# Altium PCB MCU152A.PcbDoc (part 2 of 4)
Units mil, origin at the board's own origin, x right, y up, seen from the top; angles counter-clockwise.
Board outline 2307.9 x 3007.9 mil, 4 copper layers (Top Signal, GND, PWR, Bottom Signal), stack 61.6 mil thick; 198 components, 136 nets, 740 pads, 401 vias.
Unrouted connection lines stored in the file: 147.
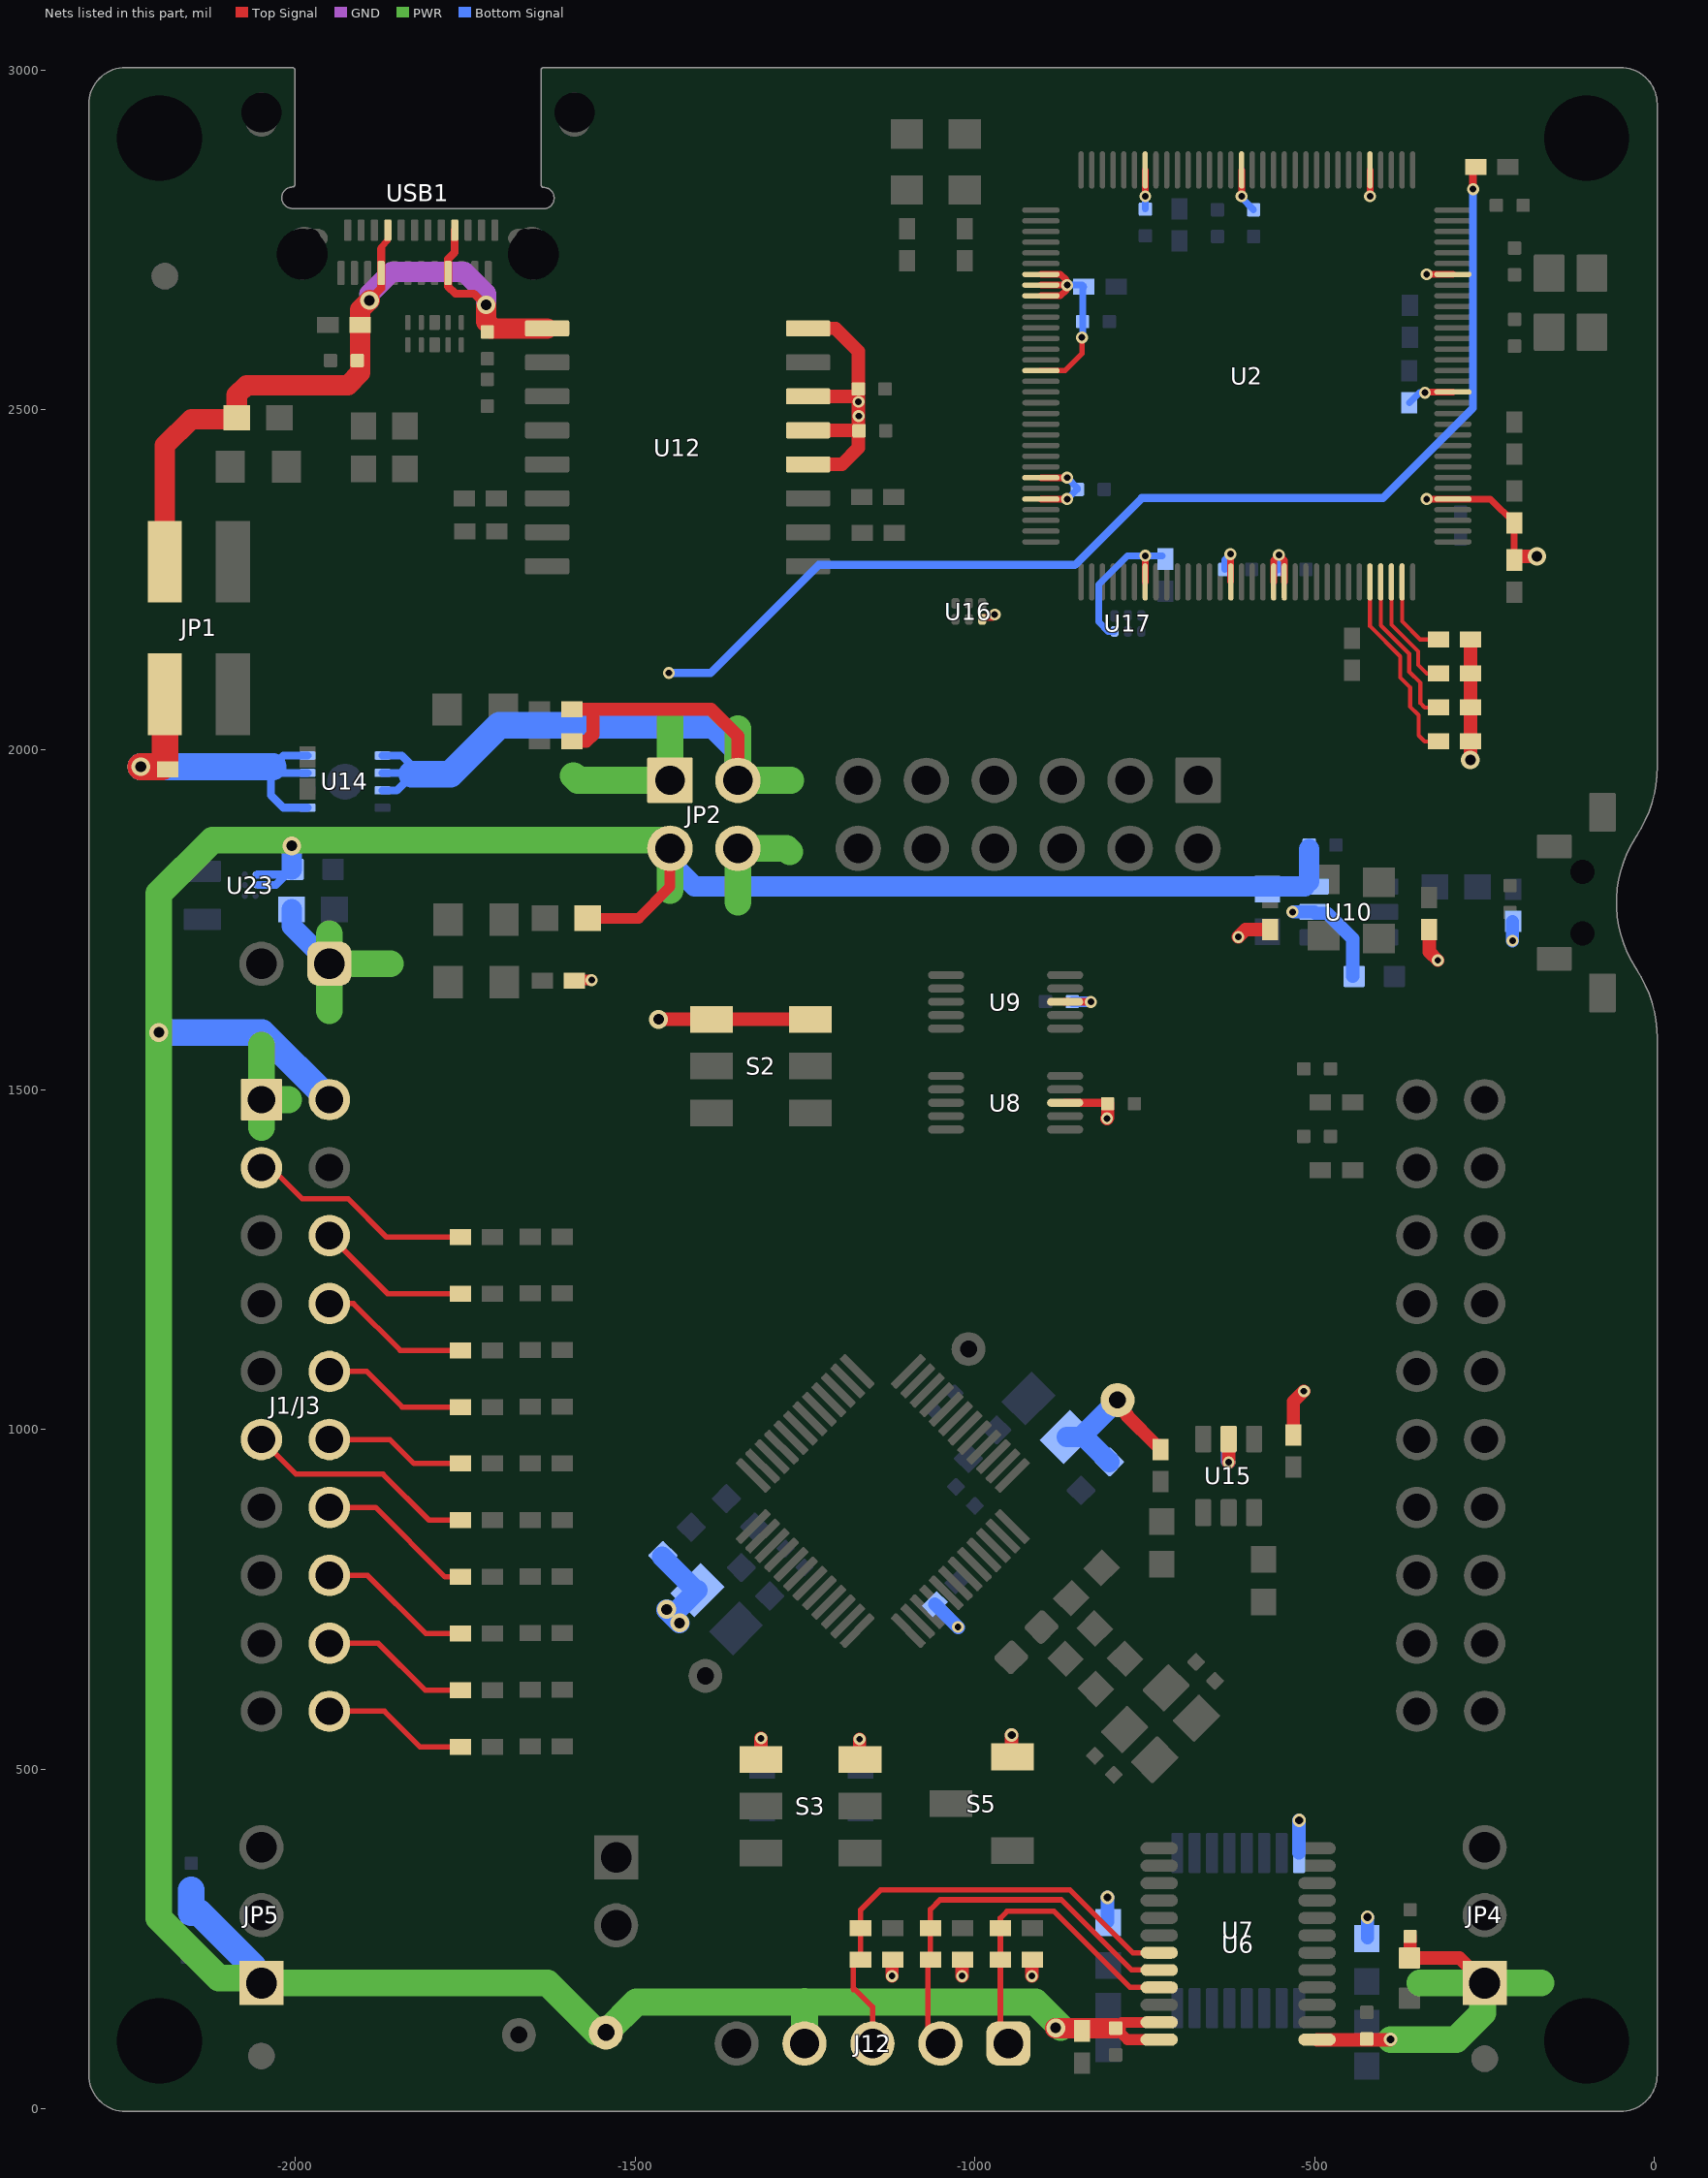
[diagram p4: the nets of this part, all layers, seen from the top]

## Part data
C1 C2 C5 C10 C11 C43 C45 C56 C57 C58 C59 C69 C70 C75 C77: library part CMP-0090362-1, "0.1µF ±10% 10V Ceramic Capacitor X7R 0402 (1005 Metric)", Digikey Part Number=732-7513-1-ND, Manufacturer="Wurth Electronics", Mouser Part Number=710-885012205018, Operating Temperature Range="-55°C to +125°C", TempCo=15%, Temperature Characteristic=X7R, Tolerance_%=10%, ValueDisplayed=100000pF
C3 C4 C78 C79: library part CMP-0124909-1, "12 pF ±2% 50V Ceramic Capacitor C0G, NP0 0402 (1005 Metric)", Digikey Part Number=732-885392005127CT-ND, Manufacturer=Wurth, Mouser Part Number=710-885392005127, Operating Temperature Range="-55°C to +125°C", TempCo=30ppm/°C, Temperature Characteristic=NP0, Tolerance_%=2%, ValueDisplayed=12pF
C6 C35 C36: library part CMP-0124925-1, "2.2 µF ±20% 10V Ceramic Capacitor X5R 0603 (1608 Metric)", Digikey Part Number=732-7908-1-ND, Manufacturer="Wurth Electronics", Mouser Part Number=710-885012106011, Operating Temperature Range="-55°C to +85°C", TempCo=15%, Temperature Characteristic=X5R, Tolerance_%=20%, ValueDisplayed=2.2uF
C7 C8 C9 C13 C14 C15 C17 C21 C22 C23: library part CMP-0006456-2, "CAP, CERM, 330 pF, 50 V, +/- 5%, C0G/NP0, 0402", Cap_Case=0402, Manufacturer=MuRata, Supplier Part Number 1=490-1295-1-ND, TempCo=C0G/NP0, Tolerance_%=5%, Value1=Unknown, Value2=50V, ValueDisplayed=330pF
C12 C18 C19 C20 C63: library part CMP-0006231-2, "CAP, CERM, 1000 pF, 50 V, +/- 10%, X7R, 0402", Cap_Case=0402, Manufacturer="Wurth Elektronik", Supplier Part Number 1=732-7556-1-ND, TempCo=X7R, Tolerance_%=10%, Value1=Unknown, Value2=50V, ValueDisplayed=1000pF
C28 C29 C30 C80 C120: library part CMP-0124926-1, "10 µF ±20% 25V Ceramic Capacitor X5R 0603 (1608 Metric)", Manufacturer=Wurth, Operating Temperature Range="-55°C to +85°C", TempCo=15%, Temperature Characteristic=X5R, Tolerance_%=20%, ValueDisplayed=10uF
C31 C32 C34 C37 C38 C81 C124: library part CMP-0090362-1, "0.1µF ±10% 10V Ceramic Capacitor X7R 0402 (1005 Metric)", Digikey Part Number=732-7513-1-ND, Manufacturer="Wurth Electronics", Mouser Part Number=710-885012205018, Operating Temperature Range="-55°C to +125°C", TempCo=15%, Temperature Characteristic=X7R, Tolerance_%=10%, ValueDisplayed=0.1uF
C60: library part CMP-0092424-1, "Cap Cer 3300pF 50V X7R 0402", Digikey Part Number=732-7559-1-ND, Manufacturer="Wurth Electronics", Mouser Part Number=710-885012205064, Operating Temperature Range="-55°C to +125°C", TempCo=15%, Temperature Characteristic=X7R, Tolerance_%=10%, ValueDisplayed=3.3nF
C62 C71 C72 C74 C76: library part CMP-0064924-2, "CAP, CERM, 1 uF, 10 V,+/- 20%, X5R, 0402", Cap_Case=0402, Manufacturer="Wurth Elektronik", Supplier Part Number 1=732-7489-1-ND, TempCo=X5R, Tolerance_%=20%, Value1=Unknown, Value2=10V, ValueDisplayed=1uF
C64: library part CMP-0006268-2, "CAP, CERM, 4.7 uF, 10 V, +/- 10%, X5R, 0402", Cap_Case=0402_065, Manufacturer=TDK, Supplier Part Number 1=445-13820-1-ND, TempCo=X5R, Tolerance_%=10%, Value1="0.003417 ohm", Value2=10V, ValueDisplayed=4.7uF
C65 C66 C67 C68 C73: library part CMP-0090363-1, "10000pF ±10% 25V Ceramic Capacitor X7R 0402 (1005 Metric)", Digikey Part Number=732-7545-1-ND, Manufacturer="Wurth Electronics", Mouser Part Number=710-885012205050, Operating Temperature Range="-55°C to +125°C", TempCo=15%, Temperature Characteristic=X7R, Tolerance_%=10%, ValueDisplayed=10000pF
C119: library part CMP-0006825-5, "CAP, CERM, 2.2 uF, 16 V, +/- 20%, X5R, 0603", Cap_Case=0603, Manufacturer="Wurth Elektronik", Supplier Part Number 1=732-7915-1-ND, TempCo=X5R, Tolerance_%=20%, Value1=Unknown, Value2=16V, ValueDisplayed=2.2uF
C125: library part CMP-0124908-1, "10000 pF ±10% 16V Ceramic Capacitor X7R 0603 (1608 Metric)", Digikey Part Number=732-7959-1-ND, Manufacturer=Wurth, Mouser Part Number=710-885012206040, Operating Temperature Range="-55°C to +125°C", TempCo=15%, Temperature Characteristic=X7R, Tolerance_%=10%, ValueDisplayed=10nF
"CE Logo1": library part CMP-0074844-1
FID1 FID2 FID3 FID4 FID5 FID6: library part CMP-0077181-1, "Fiducial mark.  There is nothing to buy or mount.", Manufacturer=N/A
H1 H2: library part CMP-0077978-1, "Spacer Support, Nylon 66", Manufacturer="Kang Yang"
J1/J3: library part CMP-0003837-4, "Receptacle, 2.54mm, 10x2, Tin, TH", Alternate Manufacturer="Major League Electronics", Alternate PartNumber=CRD-081413-A-G, Manufacturer=Samtec, Supplier Part Number 1=SAM1204-10-ND
J4/J2: library part CMP-0078266-4, "Receptacle, 2.54mm, 10x2, Tin, TH", Alternate Manufacturer="Major League Electronics", Alternate PartNumber=CRD-081413-A-G, Manufacturer=Samtec, Supplier Part Number 1=SAM1204-10-ND
J12: library part CMP-0084909-1, "Header, 2.54mm, 5x1, Gold, TH", Color=Black, Current_A=3A, Manufacturer="Wurth Elektronik", Voltage_V=250V
J15: library part CMP-0054794-1, "Header, 2.54 mm, 2x1, Gold, TH", Manufacturer="Wurth Elektronik", Supplier Part Number 1=732-5315-ND
J17: library part CMP-0054794-2, "Header, 2.54 mm, 2x1, Gold, TH", Color=Black, Manufacturer="Wurth Elektronik", Supplier Part Number 1=732-5315-ND
J101: library part CMP-0092423-1, "THT Vertical Pin Header WR-PHD, Pitch 2.54 mm, Dual Row, 12 pins", Current_A=3A, Digikey Part Number=732-5297-ND, Manufacturer="Wurth Electronics", Mouser Part Number=710-61301221121, Operating Temperature Range="-40°C to +105°C", Voltage_V=250V
JP1: library part CMP-0055559-1, "Header, 2.54mm, 2x2, Gold, SMT", Color=Black, Manufacturer=Samtec, Supplier Part Number 1=TSM-102-01-L-DV-ND, Voltage_V=475V
JP2: library part CMP-0092422-1, "THT Vertical Pin Header WR-PHD, Pitch 2.54 mm, Dual Row, 4 pins", Current_A=3A, Digikey Part Number=732-5294-ND, Manufacturer="Wurth Electronics", Mouser Part Number=710-61300421121, Operating Temperature Range="-40°C to +105°C", Voltage_V=250V
JP4 JP5: library part CMP-0054796-1, "Header, 2.54 mm, 3x1, Gold, TH", Manufacturer="Wurth Elektronik", Supplier Part Number 1=732-5316-ND
L1: library part CMP-0003073-1, "Ferrite Bead, 220 ohm @ 100 MHz, 2 A, 0805", Manufacturer="Wurth Elektronik", Supplier Part Number 1=732-1614-1-ND, Value1="0.05 ohm", Value2=2A, ValueDisplayed="220 ohm"
L2: library part CMP-0003093-1, "Ferrite Bead, 60 ohm @ 100 MHz, 3 A, 0805", Manufacturer="Wurth Elektronik", Supplier Part Number 1=732-1612-1-ND, Value1="0.025 ohm", Value2=3A, ValueDisplayed="60 ohm"
L4: library part CMP-0124907-1, "Inductor Power Shielded Multi-Layer 1uH 20% 1MHz 14Q-Factor Powdered Iron 1.2A 180mOhm DCR 0805 T/R", Digikey Part Number=732-5056-1-ND, Manufacturer=Wurth, Mouser Part Number=710-74479773210, Operating Temperature Range="-40°C to +125°C", Self Resonant Frequency=90MHz, Test Frequency=1MHz, Tolerance_%=20%
LED0 LED1 LED4 LED6 LED7: library part CMP-0002951-3, "LED, Red, SMD", Color=Red, Manufacturer="Wurth Elektronik", Power_TotalModule=72mW, Value1=0.072W, Value2=1.9V
LED2 LED3: library part CMP-0002959-3, "LED, Blue, SMD", Color=Blue, Manufacturer="Wurth Elektronik", Power_TotalModule=105mW, Value1=0.105W, Value2=3.2V
LED5: library part CMP-0003014-3, "LED, Green, SMD", Color=Green, Manufacturer="Wurth Elektronik", Power_TotalModule=105mW, Value1=0.105W, Value2=3.2V
Logo1 Logo4: library part CMP-0074838-1, "Texas Instrument Corporate Signature"
Logo2: library part CMP-0074847-1, "FCC_disclaimer"
Logo3: library part CMP-0074769-1
M4 M5 M6 M7 M8 M9 M10 M11 M12 M13: library part CMP-0003761-2, "Shunt, 2.54mm, Gold, Black", Manufacturer="Wurth Elektronik", Supplier Part Number 1=732-2678-ND
MH1 MH2 MH3 MH4: library part CMP-0078424-2, "PCB Mounting Hole, No Pad", Manufacturer=Any, PartNumber=N/A
R1 R2 R6 R21 R22 R23 R27 R28 R29 R30 R32 R33 R55 R56 R57 R58: library part CMP-0027004-2, "RES, 0, 5%, 0.063 W, 0402", Manufacturer="Yageo America", Power_W=63mW, Supplier Part Number 1=311-0.0JRCT-ND, TempCo="200 ppm/C", Tolerance_%=5%, Value2=0.063W, Value_Code=0000, ValueDisplayed=0
R3 R7: library part CMP-0026826-2, "RES, 10 M, 5%, 0.063 W, AEC-Q200 Grade 0, 0402", Manufacturer=Vishay-Dale, Power_W=63mW, Supplier Part Number 1=541-10MJCT-ND, TempCo="200 ppm/C", Tolerance_%=5%, Value2=0.063W, Value_Code=10M0, ValueDisplayed=10M
R4 R5 R62 R64: library part CMP-0026962-3, "RES, 680, 5%, 0.063 W, AEC-Q200 Grade 0, 0402", Manufacturer=Vishay-Dale, Power_W=63mW, Supplier Part Number 1=541-680JCT-ND, TempCo="200 ppm/C", Tolerance_%=5%, Value2=0.063W, Value_Code=680R, ValueDisplayed=680
R8 R9 R11 R12 R13 R14 R18 R19: library part CMP-0025697-4, "RES, 0, 5%, 0.1 W, AEC-Q200 Grade 0, 0603", Manufacturer=Vishay-Dale, Power_W=100mW, Supplier Part Number 1=541-0.0GCT-ND, TempCo="200 ppm/C", Tolerance_%=5%, Value2=0.1W, Value_Code=0000, ValueDisplayed=0
R10: library part CMP-0023387-3, "RES, 50, 0.1%, 0.125 W, 0603", Manufacturer="Vishay Thin Film", Power_W=125mW, Supplier Part Number 1=FC0603-50BFCT-ND, TempCo="25 ppm/C", Tolerance_%=0.1%, Value2=0.125W, Value_Code=50R0, ValueDisplayed=50
R15 R16: library part CMP-0022746-5, "RES, 10.0 k, 1%, 0.1 W, 0603", Manufacturer=Yageo, Power_W=100mW, Supplier Part Number 1=311-10.0KHRCT-ND, TempCo="100 ppm/C", Tolerance_%=1%, Value2=0.1W, Value_Code=10k0, ValueDisplayed=10.0k
R17: library part CMP-0025769-4, "RES, 2.2 k, 5%, 0.1 W, AEC-Q200 Grade 0, 0603", Manufacturer=Vishay-Dale, Power_W=100mW, Supplier Part Number 1=541-2.2KGCT-ND, TempCo="200 ppm/C", Tolerance_%=5%, Value2=0.1W, Value_Code=2k20, ValueDisplayed=2.2k
R24 R25 R26 R66 R67 R68 R69: library part CMP-0026071-3, "RES, 1.00 k, 1%, 0.063 W, AEC-Q200 Grade 0, 0402", Manufacturer=Vishay-Dale, Power_W=63mW, Supplier Part Number 1=541-1.00KLCT-ND, TempCo="100 ppm/C", Tolerance_%=1%, Value2=0.063W, Value_Code=1k00, ValueDisplayed=1.00k
R31 R35: library part CMP-0026890-5, "RES, 2.2 k, 5%, 0.063 W, AEC-Q200 Grade 0, 0402", Manufacturer=Vishay-Dale, Power_W=63mW, Supplier Part Number 1=541-2.2KJCT-ND, TempCo="200 ppm/C", Tolerance_%=5%, Value2=0.063W, Value_Code=2k20, ValueDisplayed=2.2k
R53: library part CMP-0026100-2, "RES, 1.00 M, 1%, 0.063 W, AEC-Q200 Grade 0, 0402", Manufacturer=Vishay-Dale, Power_W=63mW, Supplier Part Number 1=541-1.00MLCT-ND, TempCo="100 ppm/C", Tolerance_%=1%, Value2=0.063W, Value_Code=1M00, ValueDisplayed=1.00M
R54 R61: library part CMP-0025921-5, "RES, 3.0 k, 5%, 0.1 W, 0603", Manufacturer=Yageo, Power_W=100mW, Supplier Part Number 1=311-3.0KGRCT-ND, TempCo="100 ppm/C", Tolerance_%=5%, Value2=0.1W, Value_Code=3k00, ValueDisplayed=3.0k
R59 R60: library part CMP-0025932-5, "RES, 5.1 k, 5%, 0.1 W, 0603", Manufacturer=Yageo, Power_W=100mW, Supplier Part Number 1=311-5.1KGRCT-ND, TempCo="100 ppm/C", Tolerance_%=5%, Value2=0.1W, Value_Code=5k10, ValueDisplayed=5.1k
R70: library part CMP-0026824-3, "RES, 100, 5%, 0.063 W, AEC-Q200 Grade 0, 0402", Manufacturer=Vishay-Dale, Power_W=63mW, Supplier Part Number 1=541-100JCT-ND, TempCo="200 ppm/C", Tolerance_%=5%, Value2=0.063W, Value_Code=100R, ValueDisplayed=100
R71: library part CMP-0026918-5, "RES, 3.3 k, 5%, 0.063 W, AEC-Q200 Grade 0, 0402", Manufacturer=Vishay-Dale, Power_W=63mW, Supplier Part Number 1=541-3.3KJCT-ND, TempCo="200 ppm/C", Tolerance_%=5%, Value2=0.063W, Value_Code=3k30, ValueDisplayed=3.3k
R72 R73: library part CMP-0026736-1, "RES, 470, 1%, 0.063 W, 0402", Manufacturer="Yageo America", Power_W=63mW, Supplier Part Number 1=311-470LRCT-ND, TempCo="100 ppm/C", Tolerance_%=1%, Value2=0.063W, Value_Code=470R, ValueDisplayed=470
R74 R75: library part CMP-0026825-5, "RES, 10 k, 5%, 0.063 W, AEC-Q200 Grade 0, 0402", Manufacturer=Vishay-Dale, Power_W=63mW, Supplier Part Number 1=541-10KJCT-ND, TempCo="200 ppm/C", Tolerance_%=5%, Value2=0.063W, Value_Code=10k0, ValueDisplayed=10k
R76: library part CMP-0026413-2, "RES, 4.87 k, 1%, 0.063 W, AEC-Q200 Grade 0, 0402", Manufacturer=Vishay-Dale, Power_W=63mW, Supplier Part Number 1=541-4.87KLCT-ND, TempCo="100 ppm/C", Tolerance_%=1%, Value2=0.063W, Value_Code=4k87, ValueDisplayed=4.87k
R77: library part CMP-0026946-3, "RES, 51, 5%, 0.063 W, AEC-Q200 Grade 0, 0402", Manufacturer=Vishay-Dale, Power_W=63mW, Supplier Part Number 1=541-51JCT-ND, TempCo="200 ppm/C", Tolerance_%=5%, Value2=0.063W, Value_Code=51R0, ValueDisplayed=51
R94: library part CMP-0023133-5, "RES, 47.0 k, 1%, 0.1 W, 0603", Manufacturer=Yageo, Power_W=100mW, Supplier Part Number 1=311-47.0KHRCT-ND, TempCo="100 ppm/C", Tolerance_%=1%, Value2=0.1W, Value_Code=47k0, ValueDisplayed=47.0k
R95: library part CMP-0025874-4, "RES, 0, 5%, 0.1 W, AEC-Q200 Grade 0, 0603", Manufacturer=Panasonic, Power_W=100mW, Supplier Part Number 1=P0.0GCT-ND, TempCo="600 ppm/C", Tolerance_%=5%, Value2=0.1W, Value_Code=0000, ValueDisplayed=0
S1: library part CMP-0002328-1, "Switch, SPST, 0.05 A, 12 VDC, SMD", CurrentRating_mA=50A, Manufacturer=Diptronics
S2 S3: library part CMP-0002233-1, "Switch, Dual SPDT,  2 Pos, 0.1A, 6VDC, SMD", CurrentRating_mA=100A, Manufacturer="Copal Electronics", Supplier Part Number 1=CASD20JCT-ND
S5: library part CMP-0002139-2, "Switch, Slide, SPDT  100mA, SMT", CurrentRating_mA=100A, Manufacturer="Copal Electronics", Supplier Part Number 1=CAS120JCT-ND
TP2 TP3 TP4 TP5 TP6: library part CMP-0078143-3, "TEST POINT.  No entry in BOM.", Manufacturer=N/A
U1: library part CMP-0125361-1, "F28E12x Real-Time Microcontrollers", Frequency_Fixed=160MHz, Manufacturer="Texas Instruments", Max Supply Voltage=3.63V, Min Supply Voltage=2.8V, Operating Temperature Range="-40°C to +125°C"
U2: library part CMP-0077953-1, "MSP432E401YTPDT, PDT0128A (TQFP-128)", Alternate Manufacturer="Texas Instruments", Alternate PartNumber=MSP432E401YTPDTR
U6: library part CMP-0066458-2, "8-Bit Dual-Supply Bus Transceiver with Configurable Voltage-Level Shifting and Three-State Outputs, PW0024A (TSSOP-24)", Alternate Manufacturer="Texas Instruments", Operating Temperature Range="-40 to 85 C", Rating=Catalog
U7: library part CMP-0089841-1, "3 Circuit IC Switch 2:1 75Ohm 16-TSSOP", Digikey Part Number=296-3833-1-ND, Manufacturer="Texas Instruments", Max Supply Voltage=5.5V, Min Supply Voltage=2V, Mouser Part Number=595-SN74LV4053APWR, Nominal Supply Current=20uA, On State Resistance=100-225Ω, Operating Temperature Range="-40°C to +85°C"
U8 U9: library part CMP-0067418-1, "DUAL 10-Ohm SPDT ANALOG SWITCH, DGS0010A (VSSOP-10)", Alternate Manufacturer="Texas Instruments", Alternate PartNumber=TS5A23157DGST
U10: library part CMP-0120241-1, "Low-quiescent current supervisor with programmable delay and manual reset 6-SOT-23 -40 to 85", Manufacturer="Texas Instruments", Max Supply Voltage=6V, Min Supply Voltage=1.7V, Nominal Supply Current=0.6uA, Operating Temperature Range="-40°C to +125°C", Threshold Voltage=3.07V
U12: library part CMP-0091303-1, "Full/Low Speed Isolated USB Repeater, SOIC16-Wide", Manufacturer="Texas Instruments", Max Supply Voltage=5.5V, Min Supply Voltage=3V, Nominal Supply Current=9-9.5mA, Operating Temperature Range="-55°C to +150°C"
U13: library part CMP-0073613-3, "4-Channel Ultra-Low-Capacitance IEC ESD Protection Diode, DQA0010A (USON-10)", Alternate Manufacturer="Texas Instruments"
U14: library part CMP-0124913-1, "Low-Noise, Wide-Bandwidth, High PSRR, Low-Dropout 1-A Linear Regulator", Digikey Part Number=296-52139-1-ND, Dropout Voltage=500mV, Manufacturer="Texas Instruments", Max Supply Voltage=6.5V, Min Supply Voltage=3.8V, Mouser Part Number=595-TPS7A8033DRBR, Nominal Supply Current=120uA, Operating Temperature Range="-40°C to +125°C", Output Voltage=3.3V
U15: library part CMP-0051789-2, "Dual Buffer/Driver with Open-Drain Output, DBV0006A, LARGE T&R", F @ Nom Voltage(Max)(Mhz)=150, Generic Part Number=SN74LVC2G07, ICC @ Nom Voltage(Max)(mA)=0.01, Manufacturer="Texas Instruments", Operating Temperature Range(C)="-40 to 125", Rating=Catalog, tpd @ Nom Voltage(Max)(ns)=8.6,4.4,3.7,2.9, Voltage(Nom)(V)=1.8,2.5,3.3,5
U16 U17: library part CMP-0043115-3, "4-Channel ESD Protection Array for High-Speed Data Interfaces, DRY0006A (USON-6)", Breakdown Voltage(Min)(V)=6, IO Capacitance(Typ)(pF)=1.6, IO Leakage Current(nA)=1, Manufacturer="Texas Instruments", Operating Temperature Range="-40 to 85 C", Rating=Catalog
U23: library part CMP-0067212-2, "5V, 500mA, 4MHz Step-Up DC/DC Converter, YFF0006AEAE (DSBGA-6)", Alternate Manufacturer="Texas Instruments", Alternate PartNumber=TPS61241YFFT, Operating Temperature Range="-40 to 85 C", Rating=Catalog
USB1: library part CMP-0092137-1, "Connector, USB Type-C 24 pin Mid Mount dual row Receptacle Surface Mount", Manufacturer=MUP, Operating Temperature Range="-25°C to +85°C"
Y1: library part CMP-0093781-1, "20 MHz ±10ppm Crystal 8pF 50 Ohms 4-SMD, No Lead", Digikey Part Number=1923-830108207209CT-ND, Frequency Stability=20ppm, Frequency Tolerance=10ppm, Frequency_Fixed=20MHz, Load Capacitance=8pF, Manufacturer="Wurth Electronics", Mouser Part Number=710-830108207209, Operating Temperature Range="-40°C to +85°C"
Y2: library part CMP-0094478-1, "Crystal 16 MHz ±20ppm Crystal 8pF 70 Ohms 4-SMD, No Lead", Digikey Part Number=732-830064296CT-ND, Frequency Stability=20ppm, Frequency_Fixed=16MHz, Load Capacitance=8pF, Manufacturer=Wurth, Mouser Part Number=710-830064296, Operating Temperature Range="-10°C to +70°C"
ZZ1: library part CMP-0077236-1
ZZ2: library part CMP-0077237-1
ZZ3: library part CMP-0077238-1

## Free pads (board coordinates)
  round 60 on Mech5: 4(-2200,100) 4(-2050,77.66) 4(-250,73.69) 4(-100,100)

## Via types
v1: diameter 17.72, hole 9.84, Top Signal to Bottom Signal, tented both sides, 368 vias
v2: diameter 27.56, hole 15.75, Top Signal to Bottom Signal, tented both sides, 21 vias
v3: diameter 19.68, hole 11.81, Top Signal to Bottom Signal, tented both sides, 6 vias
v4: diameter 19.68, hole 7.87, Top Signal to Bottom Signal, tented both sides, 4 vias
v5: diameter 15.75, hole 7.87, Top Signal to Bottom Signal, tented both sides, 2 vias

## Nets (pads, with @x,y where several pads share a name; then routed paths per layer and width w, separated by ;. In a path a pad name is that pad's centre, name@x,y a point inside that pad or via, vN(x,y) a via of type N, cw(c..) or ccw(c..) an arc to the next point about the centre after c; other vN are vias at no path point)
+3V3_MCU: C5.2 C10.1 C28.1 C29.1 C34.1 C35.1 C43.1 C45.1 C119.1 C125.2 J1/J3.1 J17.1 JP2.4 JP4.1 L1.1 L2.1 R3.2 R4.2 R5.2 R7.2 R14.2 R17.2 R31.2 R35.2 R62.2 S2.1 S2.4 S3.3 S3.6 S5.3 TP4.1 U6.1 U7.16 U8.8 U9.8 U10.5 U15.5 | length 2754.5
  Top Signal w11.81: U8.8@-867.32,1480.5 C45.1@-806.18,1480.5 ; U9.8@-867.32,1629 v1(-829.51,1629)
  Top Signal w15.75: R62.2@-1588.62,1661 v1(-1564.04,1661)
  Top Signal w19.68: v2(-1465.7,1603.21) S2.1@-1387.69,1603.21 S2.4@-1242.02,1603.21 ; S3.6@-1314.85,514.17 v1(-1314.85,545.11) ; S3.3@-1169.85,514.81 v1(-1169.85,543.9) ; v3(-946,550) -946,512.95 S5.3@-943.5,510.45 ; v1(-805.72,1457.39) -804.68,1458.43 C45.1@-804.68,1479 ; TP4.1@-790.17,1043 -790.17,1034.8 -775.92,1020.55 -775.92,1019.51 -732.61,976.19 -728.67,976.19 -726.7,974.22 R3.2@-726.7,970.28 ; v1(-626.7,951.46) U15.5@-626.7,985.59 ; v1(-612.4,1724.53) -601.76,1735.17 R4.2@-565.85,1735.17 ; R7.2@-531.44,991.53 -531.44,1040.56 v1(-516,1056) ; U6.1@-496.25,101.39 v3@-389,101.39 ; C28.1@-360.65,221.81 -286.81,221.81 JP4.1@-250,185 ; C28.1@-359.68,224.55 C34.1@-359.68,253.55 ; R5.2@-331.49,1735.17 -331.49,1702.51 v1(-319,1690.02)
  PWR w39.37: -2050,1444 J1/J3.1@-2050,1485 ; -2050,1565 J1/J3.1@-2050,1485 ; J1/J3.1@-2048,1483 J1/J3.1@-2050,1485 ; -2010,1485 J1/J3.1@-2050,1485 ; -1950,1616 J17.1@-1950,1685 ; -1950,1729 J17.1@-1950,1685 ; -1860,1685 J17.1@-1950,1685 ; -1348.85,1775.95 JP2.4@-1348.85,1855 -1277.69,1855 -1272.69,1850 ; v3(-388.39,102) -292,102 -253,141 JP4.1@-253,185 ; -345.46,185 JP4.1@-253,185 ; -166.75,185 JP4.1@-250,185 JP4.1@-253,185
  Bottom Signal w15.75: C43.1@-856.44,1629 v1(-829.51,1629)
  Bottom Signal w19.68: R31.2@-1059.11,742.7 v1@-1024.87,708.46 ; R17.2@-805,275 v3(-805,311) ; C5.2@-627.95,981.45 -627.95,952.71 v1(-626.7,951.46) ; v1@-531,1761.32 U10.5@-500.81,1761.32 -498.85,1759.35 -481.69,1759.35 -444.05,1721.71 C125.2@-444.05,1666.45 ; U7.16@-523.18,376.36 v3@-523.18,424.5 ; R14.2@-422.47,251.52 v3(-422.47,282) ; v1(-209,1719) R35.2@-209,1746.57
  Bottom Signal w30: C119.1@-2005.5,1765 -2005.5,1740.5 J17.1@-1950,1685 ; C35.1@-1460.6,812.73 -1411.15,763.28 L2.1@-1408.17,763.28 v2@-1444.51,726.95 ; v2(-1453.65,735) -1453.65,734.09 v2(-1434.5,714.94) ; L1.1@-864.72,988.69 -838.93,988.69 C29.1@-802.12,951.88 ; L1.1@-844.48,988.69 TP4.1@-790.17,1043
  other v1: -1025,709 -532.72,1761.32
  other v3: -523,424.5
+3V3_XDS110: C58.2 C59.2 C64.1 C66.2 C67.2 C68.2 C69.2 C70.2 C71.1 C72.1 C73.2 JP2.3 R64.2 R66.2 R67.2 R68.2 R69.2 R71.2 R74.2 R77.2 U2.7 U2.8 U2.9 U2.16 U2.26 U2.28 U2.39 U2.47 U2.51 U2.52 U2.69 U2.79 U2.90 U2.101 U2.113 U2.122 U12.12 U12.13 U12.14 U12.16 U14.1 U14.2 U14.3 U16.6 U17.6 | length 3292.7
  Top Signal w7.87: U2.16@-902.95,2557.87 -867.52,2557.87 -842.6,2582.8 v1(-842.6,2606.65)
  Top Signal w10: U16.6@-986.44,2194.79 -973.21,2194.79 -971,2197 v1(-971,2199) ; U2.28@-902.95,2368.9 v1(-864.29,2368.9) ; U2.26@-902.95,2400.39 v1(-864.29,2400.39) ; U2.9@-902.95,2668.11 -874,2668.11 -865.77,2676.34 -865.77,2682.38 v1(-864.29,2683.86) ; U2.8@-902.95,2683.86 v1(-864.29,2683.86) ; U2.7@-902.95,2699.61 -874,2699.61 -865.77,2691.37 -865.77,2685.33 v1(-864.29,2683.86) ; U2.39@-749.41,2246.85 v1(-749.41,2285.51) ; v1(-749.41,2814.49) U2.122@-749.41,2853.15 ; U2.47@-623.99,2247.42 v1(-623.99,2288) ; v1(-607.68,2814.49) U2.113@-607.68,2853.15 ; U2.51@-560.43,2246.85 -560.43,2279.02 v1(-552.8,2286.65) -544.68,2278.54 U2.52@-544.68,2246.85 ; v1(-418.7,2814.49) U2.101@-418.7,2853.15 ; v1@-336.69,2526.1 U2.79@-296.42,2526.1 ; v1(-335.31,2368.9) U2.69@-296.65,2368.9 -241.42,2368.9 R74.2@-205.98,2333.46 ; v1(-335.31,2699.61) U2.90@-296.65,2699.61 ; R77.2@-206.34,2279.21 -206.34,2333.11 R74.2@-205.98,2333.46 ; R74.2@-203.31,2336.14 R74.2@-205.98,2333.46
  Top Signal w19.68: C64.1@-1593.34,2012.39 -1572.11,2012.39 -1562,2022.5 -1562,2059.39 ; R64.2@-1593.34,2059.39 -1562,2059.39 ; JP2.3@-1348.85,1955 -1348.85,2019.85 -1388.39,2059.39 -1562,2059.39 ; U12.12@-1245.63,2420 -1195.51,2420 -1171.42,2444.09 C59.2@-1171.42,2470 ; U12.13@-1245.63,2470 C59.2@-1171.42,2470 ; U12.14@-1245.63,2520 v1@-1174.76,2520 ; U12.16@-1245.63,2620 -1205.28,2620 -1171.42,2586.14 C59.2@-1171.42,2470 ; C59.2@-1170.67,2469.37 -1171.3,2470 C59.2@-1171.42,2470 ; v2(-271,1985) -271,2062.21 R66.2@-271,2161.83 ; R77.2@-201.13,2284.42 v2(-173,2284.42)
  PWR w30: JP2.3@-1348.85,1945 JP2.3@-1348.85,1955
  PWR w39.37: -1348.85,2030.88 JP2.3@-1348.85,1955 -1271.29,1955
  Bottom Signal w10: v1(-864.29,2368.9) -850.08,2383.11 C70.2@-849.25,2383.11 -849.25,2385.35 v1(-864.29,2400.39) ; v1(-864.29,2683.86) -842.09,2683.86 C72.1@-839.65,2681.42 -841.3,2679.76 -841.3,2606.06 -841.89,2606.65 v1(-842.6,2606.65) ; U17.6@-794.69,2174.19 -804.19,2174.19 -818,2188 -818,2243 -775.49,2285.51 v1(-749.41,2285.51) R71.2@-724.71,2285.51 ; v1(-749.41,2814.49) -749.41,2795.79 C67.2@-749.21,2795.59 ; C69.2@-632.32,2265.28 -632.32,2279.67 v1(-623.99,2288) v1@-623.99,2284.94 ; v1(-607.68,2814.49) -607.68,2812.36 C66.2@-590,2794.68 ; C71.1@-360.79,2510.51 -345.83,2525.47 v1(-337.83,2525.47)
  Bottom Signal w11.81: U14.3@-1871.88,1940.2 -1850.8,1940.2 -1835,1956 ; U14.2@-1871.88,1965.8 -1844.8,1965.8 ; U14.1@-1871.88,1991.39 -1843.39,1991.39 -1833,1981 -1833,1957 ; C68.2@-554.41,2265.28 -552.8,2266.89 v1(-552.8,2286.65)
  Bottom Signal w39.37: -1829,1964 -1772,1964 -1700,2036 -1384.68,2036 -1348.85,2000.17 JP2.3@-1348.85,1955
  other v1: -1171,2491 -1171.3,2512
+5V0_MCU: C11.2 C12.1 C80.1 C81.1 C120.1 C124.1 J1/J3.21 J12.4 JP2.2 JP5.1 R24.2 R25.2 R26.2 R61.2 R94.2 TP5.1 U6.23 U6.24 U10.6 U23.B2 U23.C2 | length 5969.7
  Top Signal w15.75: R61.2@-1569.77,1752 -1495,1752 -1448.85,1798.15 JP2.2@-1448.85,1855 ; U6.24@-728.89,101.75 -776.07,101.75 C11.2@-793,118.68 -784.34,127.34 U6.23@-728.89,127.34
  Top Signal w19.68: v1(-1122,195.25) R26.2@-1122,218.73 ; v1(-1019,195.25) R25.2@-1019,218.73 ; v1(-916.27,195.25) R24.2@-916.27,218.73
  Top Signal w30: v2@-882,118.68 C11.2@-793,118.68
  PWR w39.37: JP5.1@-2053,185 -1629,185 -1556.22,112.22 TP5.1@-1543,112.22 -1498.22,157 -911,157 v2@-874,120 ; JP5.1@-2050,185 -2057.15,192.15 -2112.59,192.15 -2201,280.56 v2(-2201,1584) -2201,1788.18 -2122.18,1867 -2005.44,1867 -1460.85,1867 JP2.2@-1448.85,1855 -1448.85,1793.15 ; J12.4@-1250.8,95.98 -1250.8,157.8
  Bottom Signal w11.81: U23.C2@-2056,1816.48 -2013.01,1816.48 -2028.58,1800.92 U23.B2@-2054.8,1800.92
  Bottom Signal w30: C120.1@-2005.5,1824 -2005.5,1856.5 v2@-2005,1857 ; JP2.2@-1448.85,1855 -1448.85,1835.13 -1412.41,1798.68 U10.6@-514.91,1798.68 ; U10.6@-508.14,1806.04 C124.1@-508.14,1854.04
  Bottom Signal w39.37: v2(-2201,1584) -2049,1584 J1/J3.21@-1950,1485 ; C81.1@-2153.25,321.88 C80.1@-2153.25,288.46 -2141.46,288.46 -2062.8,209.8 -2062.8,197.8 JP5.1@-2050,185
  other v2: -881,119 -2005.44,1858.56
+5V0_USB: C56.2 C60.2 JP1.1 R53.2 R54.2 U12.1 USB1.A4 USB1.A9 USB1.B4 USB1.B9 | length 1257.4
  Top Signal w5.98: -1875.82,2739.25 USB1.B4@-1865.82,2750.15
  Top Signal w7.87: -1873.4,2739.25 -1870.82,2742.07 -1863.98,2748.91 USB1.B4@-1863.98,2764.57
  Top Signal w11.81: v2@-1890.54,2662.25 -1873.82,2678.98 USB1.A9@-1873.82,2701.58 -1873.82,2737.01 ; USB1.B9@-1765.55,2764.57 -1765.55,2731.86 -1775.39,2722.02 USB1.A4@-1775.39,2701.58 -1775.39,2681.83 -1764.51,2670.95 -1737.49,2670.95 v2@-1717.56,2651.02 ; C56.2@-1712.24,2620 C56.2@-1710.57,2621.67
  Top Signal w30: JP1.1@-2191.97,2276.44 -2191.97,2447.6 -2153.23,2486.34 R54.2@-2089.49,2486.34 ; R54.2@-2086.3,2488.35 -2086.3,2521.73 -2071.42,2536.61 -1922.91,2536.61 -1905,2554.53 R53.2@-1905,2625 -1905,2647.45 v2@-1890.74,2661.71 ; v2@-1719,2652.36 -1719,2630.1 C56.2@-1710.57,2621.67 ; C56.2@-1712.24,2620 U12.1@-1629.49,2620
  GND w30: v2(-1890.91,2660.98) -1890.91,2670.59 -1858.46,2703.03 -1751.61,2703.03 -1719.33,2670.75 v2(-1719.33,2654.68)
+5V0_XDS110: C62.1 JP1.2 JP2.1 R70.1 U14.5 U14.7 U14.8 | length 2470.5
  Top Signal w11.81: v1@-267.32,2825 -267.32,2853.5 R70.1@-262.91,2857.91
  Top Signal w39.37: v2(-2227.5,1975) -2195.97,1975 -2191.97,1979 JP1.2@-2191.97,2081.56
  PWR w39.37: -1591,1962.07 -1583.93,1955 JP2.1@-1448.85,1955 -1448.85,2045.75
  Bottom Signal w11.81: -2036,1964 -2036,1933 -2017.61,1914.61 U14.5@-1982.12,1914.61 ; -2032,1974 -2026.58,1974 -2018.38,1965.8 U14.7@-1982.12,1965.8 ; -2030,1979 -2017.61,1991.39 U14.8@-1982.12,1991.39 ; v1(-1450.5,2113) -1389,2113 -1230.02,2271.98 -853.02,2271.98 -754.53,2370.47 -399.61,2370.47 -267.32,2502.76 v1@-267.32,2825
  Bottom Signal w39.37: v2(-2227.5,1975) -2033,1975
  other v1: -267,2825
ADCINA0/CMPDAC/PGA1_INM2: J1/J3.30 R6.1 | length 214.4
  Top Signal w7.87: J1/J3.30@-1950,585 -1868.98,585 -1816.77,532.79 R6.1@-1757.26,532.79
ADCINA4/PGA1_INM1: J1/J3.2 R21.1 | length 335.1
  Top Signal w7.87: J1/J3.2@-2050,1385 -2035.86,1385 -1990.14,1339.28 -1922.48,1339.28 -1865.99,1282.79 R21.1@-1757.26,1282.79
ADCINA5: J1/J3.24 R22.1 | length 221.3
  Top Signal w7.87: J1/J3.24@-1950,1185 -1914.65,1185 -1845.77,1116.12 R22.1@-1757.26,1116.12
ADCINA7: J1/J3.6 R23.1 | length 342
  Top Signal w7.87: J1/J3.6@-2050,985 -1999,934 -1871,934 -1803.12,866.12 R23.1@-1757.26,866.12
ADCINA8/PGA1_OUT: J1/J3.23 R27.1 | length 228.2
  Top Signal w7.87: J1/J3.23@-1950,1285 -1864.46,1199.46 R27.1@-1757.26,1199.46
ADCINA11/PGA1_INP1: J1/J3.27 R28.1 | length 235.1
  Top Signal w7.87: J1/J3.27@-1950,885 -1882,885 -1779.79,782.79 R28.1@-1757.26,782.79
ADCINA12: J1/J3.25 R29.1 | length 214.4
  Top Signal w7.87: J1/J3.25@-1950,1085 -1895,1085 -1842.79,1032.79 R29.1@-1757.26,1032.79
ADCINA14/A15: J1/J3.26 R30.1 | length 207.5
  Top Signal w7.87: J1/J3.26@-1950,985 -1861,985 -1825.46,949.46 R30.1@-1757.26,949.46
ADCINA16/PGA1_INP2: J1/J3.28 R33.1 | length 228.2
  Top Signal w7.87: J1/J3.28@-1950,785 -1894,785 -1808.46,699.46 R33.1@-1757.26,699.46
ADCINA21/PGA1_INP3/A6: J1/J3.29 R32.1 | length 221.3
  Top Signal w7.87: J1/J3.29@-1950,685 -1878,685 -1809.12,616.12 R32.1@-1757.26,616.12
DEBUG_ID4: R66.1 U2.63 | length 122.7
  Top Signal w5.91: U2.63@-371.46,2246.85 -371.46,2188.75 -344.92,2162.21 R66.1@-317.86,2162.21
DEBUG_ID5: R67.1 U2.62 | length 173.5
  Top Signal w5.91: U2.62@-387.2,2246.85 -387.2,2184.2 -348,2145 -348,2125 -335.21,2112.21 R67.1@-317.86,2112.21
DEBUG_ID6: R68.1 U2.61 | length 231.8
  Top Signal w5.91: U2.61@-402.95,2246.85 -402.95,2182.95 -361,2141 -361,2115 -344.54,2098.54 -344.54,2068.54 -338.21,2062.21 R68.1@-317.86,2062.21
DEBUG_ID7: R69.1 U2.60 | length 288.3
  Top Signal w5.91: U2.60@-418.7,2246.85 -418.7,2182 -374,2137.3 -374,2106 -359.68,2091.68 -359.68,2063.68 -347,2051 -347,2021 -338.21,2012.21 R69.1@-317.86,2012.21
EQEP1A: C18.1 J12.1 R24.1 U6.21 | length 472.3
  Top Signal w7.87: J12.1@-962.62,104.8 R24.1@-962.62,211.38 ; J12.1@-962.62,107.8 J12.1@-950.8,95.98 ; R24.1@-962.62,216 C18.1@-962.62,266 -962.62,280.7 -952.65,290.68 -883.68,290.68 -771.52,178.52 U6.21@-728.89,178.52
EQEP1B: C19.1 J12.2 R25.1 U6.20 | length 588.7
  Top Signal w7.87: J12.2@-1069.35,111.54 J12.2@-1069.35,114.54 ; R25.1@-1069.35,211.38 J12.2@-1069.35,114.54 ; R25.1@-1065.35,216 C19.1@-1065.35,266 -1065.35,293.55 -1051.4,307.5 -873,307.5 -769.61,204.11 U6.20@-728.89,204.11 ; J12.2@-1050.8,95.98 J12.2@-1069.35,114.54
EQEP1I: C20.1 J12.3 R26.1 U6.19 | length 705
  Top Signal w7.87: -1179.35,175.57 -1179.35,178.57 ; R26.1@-1179.35,219.62 -1179.35,178.57 ; R26.1@-1168.35,216 C20.1@-1168.35,266 -1168.35,281.78 -1168.35,292.78 -1139.13,322 -860,322 -767.7,229.7 U6.19@-728.89,229.7 ; J12.3@-1150.8,95.98 -1150.8,150.01 -1179.35,178.57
